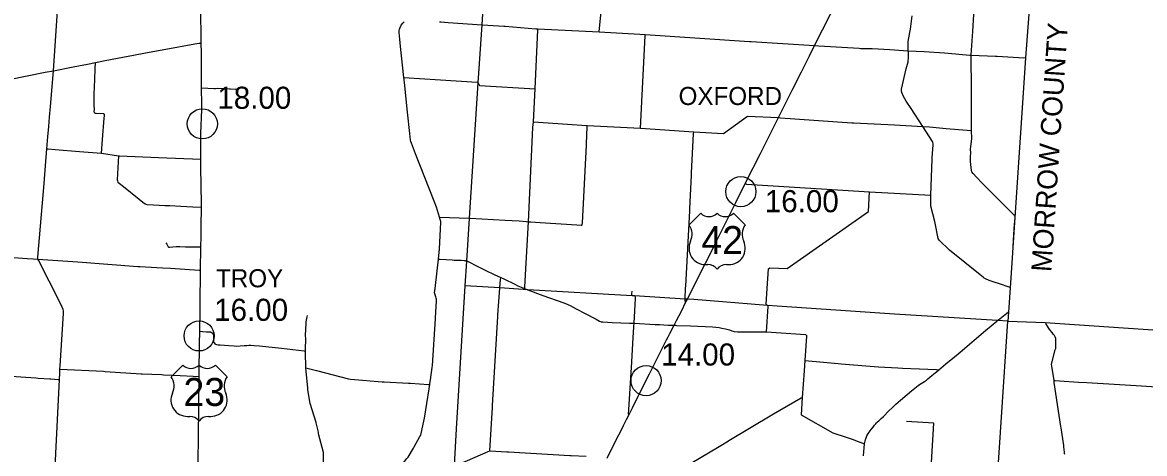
# Model space of a CAD drawing. Extents: x 1597222 to 1925846, y 496284 to 911751.
# Drawn here: x 1799698 to 1855559, y 852560 to 874016 of the extents above; entities that cross this region are included whole.
import ezdxf

# ---------------------------------------------------------------- set-up
doc = ezdxf.new("R2010")
doc.units = 0
for name, color, linetype in [('Default', 7, 'Continuous'), ('GM_X_Adjacent_County_Text', 7, 'Continuous'), ('GM_X_County', 7, 'Continuous'), ('GM_X_County_Road', 7, 'Continuous'), ('GM_X_Township', 7, 'Continuous'), ('GM_X_Township_Road', 7, 'Continuous'), ('GM_X_Township_Text', 7, 'Continuous'), ('GM_X_US_Route', 7, 'Continuous'), ('GM_X_US_Shield', 7, 'Continuous')]:
    doc.layers.add(name, color=color, linetype=linetype)

msp = doc.modelspace()

# ---------------------------------------------------------------- linework, layer by layer
at = {"layer": 'Default'}
for centre in [(1808652, 868968), (1835461, 865595), (1808492, 858414), (1830743, 856190)]:
    msp.add_circle(centre, 750, dxfattribs=at)
at = {"layer": 'GM_X_County'}
msp.add_lwpolyline([(1850017, 877290), (1849634, 872258), (1849106, 864311), (1848864, 860810), (1848787, 859601), (1848752, 859146), (1850615, 859080), (1861827, 858324)], dxfattribs=at)
at = {"layer": 'GM_X_County_Road'}
for points in [[(1801238, 871613), (1801481, 875086), (1801483, 875120), (1801484, 875131)], [(1844920, 865421), (1844988, 867215), (1844990, 867274), (1845035, 867925), (1845034, 867981), (1845022, 868042), (1845000, 868095), (1844527, 868834), (1843932, 869740), (1843693, 870106), (1843565, 870325), (1843478, 870530), (1843453, 870621), (1843455, 870702), (1843691, 871703), (1843783, 872054), (1843799, 872125), (1843808, 872218), (1843813, 872294), (1843800, 872513), (1843796, 872610), (1843794, 872719), (1843797, 872872), (1843799, 873058), (1843810, 873171), (1843903, 873683), (1843995, 874339)], [(1820462, 864324), (1820315, 864828), (1820199, 865126), (1819267, 867478), (1819059, 868009), (1819037, 868087), (1819024, 868161), (1818988, 868490), (1818871, 869545), (1818714, 871024), (1818688, 871275), (1818522, 872824), (1818481, 873185), (1818449, 873518), (1818456, 873613), (1818468, 873675), (1818498, 873766), (1818559, 873888), (1818627, 873984), (1818695, 874040)], [(1824699, 860768), (1824709, 860807), (1824715, 860860), (1824883, 864100), (1825114, 868796), (1825134, 869072), (1825228, 870716), (1825347, 873642), (1825350, 873697)], [(1825350, 873697), (1828404, 873550), (1830426, 873436), (1830706, 873421), (1835899, 873073), (1835968, 873069), (1839135, 872864)], [(1796250, 870609), (1800830, 871534), (1801238, 871613), (1802216, 871813), (1802942, 871947), (1803327, 872024), (1803819, 872121), (1804436, 872238), (1805225, 872387), (1805820, 872499), (1807386, 872793), (1807725, 872855), (1808371, 872970), (1808499, 872991), (1808602, 872989)], [(1839135, 872864), (1839344, 872852), (1841345, 872730), (1841421, 872727), (1842003, 872716), (1842870, 872667), (1843552, 872620), (1843796, 872610)], [(1801567, 856755), (1801567, 856755), (1801584, 856930), (1801742, 859524), (1801746, 859662), (1801732, 859727), (1801677, 859846), (1801556, 860087), (1800489, 862190), (1800471, 862240), (1800469, 862342), (1800776, 866006), (1800811, 866452), (1800848, 866888), (1800911, 867730), (1800965, 868323), (1801008, 868838), (1801046, 869299), (1801092, 869835), (1801238, 871613)], [(1848869, 860822), (1848289, 861017), (1848127, 861070), (1847820, 861177), (1847644, 861252), (1847581, 861290), (1847540, 861317), (1847370, 861450), (1845855, 862679), (1845795, 862727), (1845378, 863132), (1845338, 863172), (1845282, 863256), (1845130, 864033), (1845116, 864109), (1844927, 864878), (1844914, 864930), (1844919, 865353), (1844920, 865421)], [(1819979, 856052), (1820004, 856221), (1820093, 856849), (1820106, 856948), (1820253, 859267), (1820256, 859321), (1820308, 860164), (1820312, 860243), (1820295, 860293), (1820272, 860358), (1820219, 860562), (1820238, 860767), (1820341, 861658), (1820408, 862232), (1820454, 862755), (1820524, 864057), (1820528, 864114), (1820480, 864265), (1820462, 864324)], [(1820408, 862232), (1820494, 862231), (1821085, 862203), (1821196, 862192), (1821533, 862179), (1821692, 862169), (1821732, 862161)], [(1821732, 862161), (1821747, 862158), (1821783, 862149), (1821820, 862138), (1821852, 862127), (1822363, 861870), (1822764, 861678), (1823175, 861477), (1823506, 861322), (1823697, 861236), (1824174, 861011), (1824367, 860911), (1824699, 860768)], [(1824699, 860768), (1824857, 860710), (1825612, 860430), (1826656, 860059), (1826853, 859982), (1826971, 859934), (1827258, 859768), (1827710, 859527), (1828254, 859247), (1828432, 859153), (1828513, 859123), (1828584, 859112), (1829052, 859088), (1829917, 859051), (1830145, 859048), (1831204, 858991), (1831412, 858982), (1831846, 858956), (1831978, 858953), (1832140, 858950)], [(1813792, 857659), (1813794, 857827), (1813800, 858197), (1813802, 858295), (1813794, 858400), (1813790, 858459), (1813824, 859039), (1813828, 859109), (1813877, 859368), (1813888, 859424)], [(1841560, 852444), (1841625, 853051), (1841645, 853178), (1841666, 853257), (1841678, 853296), (1841734, 853436), (1841775, 853522), (1841811, 853578), (1841852, 853630), (1841955, 853751), (1842050, 853872), (1842120, 853970), (1842174, 854044), (1842213, 854090), (1842257, 854132), (1842328, 854190), (1842398, 854247), (1842454, 854298), (1842569, 854408), (1842835, 854682), (1843009, 854858), (1843082, 854926), (1843184, 855026), (1843290, 855116), (1843408, 855218), (1843743, 855499), (1843955, 855674), (1844282, 855947), (1844355, 856000), (1844431, 856051), (1844597, 856149), (1844696, 856217), (1844777, 856277), (1844977, 856441), (1845142, 856580), (1845198, 856628), (1845320, 856733), (1845665, 857022), (1846093, 857374), (1846284, 857524), (1846382, 857614), (1847073, 858199), (1847645, 858684), (1848208, 859149), (1848243, 859177), (1848285, 859211), (1848293, 859218)], [(1848293, 859218), (1848788, 859619)], [(1808526, 858649), (1808657, 858638), (1808859, 858626), (1809019, 858618), (1809052, 858615), (1809095, 858599), (1809143, 858567), (1809166, 858544), (1809192, 858504), (1809208, 858460), (1809213, 858422), (1809211, 858321), (1809207, 858185), (1809213, 858132), (1809225, 858094), (1809243, 858063), (1809274, 858027), (1809305, 858005), (1809359, 857983), (1809445, 857973), (1809547, 857964), (1809965, 857932), (1810245, 857914), (1810373, 857908), (1810529, 857918), (1810728, 857939), (1810862, 857945), (1810963, 857947), (1811066, 857950), (1811236, 857941), (1811500, 857918), (1812600, 857811), (1813718, 857665), (1813792, 857659)], [(1832140, 858950), (1832225, 858943), (1832265, 858939), (1832961, 858909), (1834057, 858860), (1834388, 858837), (1834514, 858807), (1834697, 858768), (1834897, 858714), (1835014, 858675), (1835136, 858637), (1835294, 858625), (1835692, 858625), (1836196, 858623), (1836448, 858626), (1836739, 858621)], [(1836739, 858621), (1838675, 858491), (1838704, 858476), (1838715, 858460)], [(1851584, 852517), (1851577, 852569), (1851568, 852637), (1851545, 852900), (1851540, 852956), (1851400, 853843), (1851390, 853908), (1851065, 856102), (1851052, 856192), (1850945, 856903), (1850930, 857004), (1851117, 857720), (1851136, 857792), (1851143, 857929), (1851137, 858286), (1851111, 858362), (1851070, 858431), (1851029, 858488), (1850952, 858587), (1850847, 858724), (1850809, 858773), (1850694, 858953), (1850650, 859027)], [(1838715, 858460), (1838725, 858446), (1838731, 858409), (1838644, 857189), (1838612, 856680), (1838509, 855352), (1838468, 854485), (1840033, 853588), (1840704, 853369), (1840998, 853268), (1841304, 853162), (1841625, 853051)], [(1813810, 856819), (1813800, 856979), (1813794, 857454), (1813792, 857659)], [(1801549, 856244), (1801549, 856244), (1801565, 856560), (1801567, 856755)], [(1801567, 856755), (1803730, 856654), (1803812, 856649), (1805603, 856528), (1805663, 856523)], [(1813810, 856819), (1814272, 856708), (1814342, 856691), (1815928, 856285), (1816023, 856260), (1817602, 856132), (1817706, 856124), (1818919, 856063), (1819010, 856058), (1819906, 856004), (1819971, 856000)], [(1814317, 854102), (1814022, 855049), (1813998, 855126), (1813913, 855754), (1813904, 855818), (1813815, 856658), (1813810, 856819)], [(1801256, 850553), (1801549, 856244)], [(1816452, 847455), (1816586, 847751), (1818021, 850937), (1818081, 851052), (1818426, 851791), (1818463, 851867), (1818600, 852027), (1818667, 852103), (1818835, 852306), (1818895, 852378), (1819166, 852831), (1819205, 852895), (1819487, 853403), (1819531, 853481), (1819699, 854255), (1819715, 854325), (1819940, 855787), (1819971, 856000), (1819979, 856052)], [(1814694, 851004), (1814695, 851266), (1814689, 851950), (1814688, 852505), (1814683, 852620), (1814444, 853547), (1814429, 853618), (1814335, 854030), (1814321, 854092), (1814317, 854102)]]:
    msp.add_lwpolyline(points, dxfattribs=at)
at = {"layer": 'GM_X_Township'}
for points in [[(1850017, 877290), (1849634, 872258), (1849106, 864311), (1848864, 860810), (1848787, 859601), (1848752, 859146), (1848243, 859177), (1843111, 859493), (1837275, 859897), (1836785, 859928), (1833125, 860220), (1832799, 860239), (1832694, 860243), (1830166, 860402), (1830089, 860410), (1830057, 860416), (1824857, 860710), (1823464, 860801), (1821743, 860915), (1821820, 862138), (1821956, 864281), (1822382, 871013), (1822583, 873901), (1822822, 877662)], [(1820182, 834021), (1820274, 835623), (1820357, 837080), (1820411, 838018), (1820789, 844650), (1820950, 847472), (1821204, 851968), (1821306, 853784), (1821743, 860915)], [(1858606, 831851), (1854821, 832136), (1851310, 832334), (1849737, 832422), (1846971, 832575), (1847065, 833986), (1848030, 848046), (1848128, 849585), (1848752, 859146), (1850615, 859080), (1861827, 858324)]]:
    msp.add_lwpolyline(points, dxfattribs=at)
at = {"layer": 'GM_X_Township_Road'}
for points in [[(1828404, 873550), (1828535, 874900), (1828545, 874985), (1828797, 877614), (1828805, 877701), (1828926, 878930)], [(1846952, 868642), (1846950, 869189), (1846940, 869904), (1846940, 870264), (1846936, 871157), (1846927, 871876), (1846924, 872189), (1846924, 872391), (1846924, 872409), (1846974, 873096), (1847017, 873560), (1847077, 874700), (1847167, 875719), (1847252, 876799), (1847310, 877457)], [(1820460, 874051), (1820518, 874039), (1820891, 874015), (1822583, 873901), (1822593, 873900)], [(1822593, 873900), (1823661, 873833), (1823727, 873829), (1825253, 873705), (1825350, 873697)], [(1830464, 868756), (1830701, 873344), (1830706, 873421)], [(1843796, 872610), (1844591, 872563), (1845606, 872508), (1846865, 872395), (1846924, 872391), (1848139, 872336), (1848226, 872331), (1849545, 872262), (1849640, 872268)], [(1803268, 870443), (1803301, 871169), (1803323, 871703), (1803327, 872024)], [(1818688, 871275), (1822342, 871039), (1822367, 871038)], [(1822367, 871038), (1822368, 871038), (1822382, 871013), (1822458, 870878), (1825228, 870716)], [(1803630, 867510), (1803691, 868196), (1803773, 869260), (1803782, 869375), (1803783, 869405), (1803781, 869425), (1803775, 869439), (1803764, 869452), (1803746, 869464), (1803713, 869468), (1803374, 869487), (1803312, 869492), (1803294, 869504), (1803281, 869529), (1803275, 869558), (1803280, 869733), (1803274, 869853), (1803267, 870424), (1803268, 870443)], [(1808615, 870762), (1809236, 870737), (1809316, 870737), (1809432, 870743), (1809843, 870725), (1810007, 870717), (1810039, 870714), (1810063, 870708), (1810302, 870697), (1810369, 870694)], [(1825134, 869072), (1827790, 868881), (1827808, 868880), (1830464, 868756), (1833115, 868570), (1834606, 868488), (1835796, 869350), (1837331, 869279), (1837434, 869271)], [(1837434, 869271), (1840984, 869021), (1841014, 869019), (1841088, 869014), (1843104, 868927), (1844527, 868834), (1844860, 868817), (1845680, 868730), (1846299, 868685), (1846723, 868656), (1846952, 868642)], [(1824883, 864100), (1825008, 864087), (1825479, 864057), (1827301, 863943), (1827512, 863928), (1827528, 863927), (1827544, 863932), (1827556, 863942), (1827563, 863956), (1827574, 864035), (1827772, 867912), (1827777, 867978), (1827806, 868822), (1827808, 868880)], [(1847190, 866322), (1847029, 866494), (1846966, 866586), (1846940, 866643), (1846902, 867096), (1846899, 867328), (1846913, 867520), (1846901, 867711), (1846907, 867849), (1846949, 868098), (1846958, 868238), (1846952, 868642)], [(1832712, 860086), (1832692, 860180), (1832694, 860243), (1832711, 860815), (1832717, 860894), (1832916, 864638), (1832920, 864735), (1833003, 866422), (1833008, 866525), (1833111, 868476), (1833115, 868570)], [(1800911, 867730), (1800986, 867727), (1801330, 867699), (1802540, 867596), (1803630, 867510), (1804477, 867384), (1804498, 867383), (1804527, 867381)], [(1804477, 867384), (1804421, 866175), (1804424, 866127), (1804449, 866069), (1804513, 866012), (1804732, 865849), (1805503, 865225), (1805691, 865068), (1805810, 864983), (1805846, 864967), (1805905, 864963), (1806229, 864943), (1806794, 864904), (1807037, 864899), (1807575, 864865), (1808185, 864842), (1808605, 864823)], [(1804527, 867381), (1806474, 867297)], [(1806474, 867297), (1808579, 867207)], [(1835681, 865996), (1835751, 865973), (1841870, 865582), (1844920, 865421)], [(1849108, 864379), (1849086, 864409), (1849077, 864422), (1849056, 864444), (1848707, 864795), (1848132, 865354), (1847476, 866016), (1847190, 866322)], [(1836801, 859906), (1836785, 859928), (1836730, 860003), (1836772, 860771), (1836832, 861759), (1836900, 861806), (1837774, 861777), (1841815, 864609), (1841870, 865582)], [(1820462, 864324), (1821937, 864282)], [(1821937, 864282), (1821956, 864281), (1821991, 864279), (1823727, 864175), (1824431, 864135), (1824774, 864114), (1824883, 864100)], [(1849021, 862856), (1849057, 863463), (1849090, 863978), (1849102, 864092), (1849117, 864321), (1849117, 864329), (1849117, 864338), (1849117, 864343), (1849117, 864351), (1849116, 864355), (1849116, 864358), (1849115, 864361), (1849113, 864368), (1849111, 864373), (1849108, 864379)], [(1795573, 862604), (1795573, 862604), (1798801, 862345), (1799934, 862267), (1800231, 862253), (1800471, 862240)], [(1806832, 863051), (1806885, 862986), (1806910, 862940), (1806928, 862878), (1806946, 862853), (1806969, 862836), (1807015, 862834), (1807358, 862860), (1807384, 862860), (1807529, 862858), (1807823, 862841), (1807878, 862841), (1808114, 862844), (1808408, 862851), (1808584, 862855)], [(1800471, 862240), (1802462, 862095), (1805449, 861870), (1805545, 861864), (1806678, 861809), (1807065, 861779), (1808492, 861691), (1808564, 861690)], [(1823464, 860797), (1823464, 860801), (1823489, 861218), (1823506, 861322)], [(1822973, 852697), (1823090, 854855), (1823095, 854950), (1823360, 859378), (1823364, 859462), (1823464, 860797)], [(1830145, 859048), (1830219, 860280), (1830222, 860351), (1830198, 860382), (1830166, 860402), (1830089, 860410), (1830057, 860416), (1830033, 860449), (1830040, 860509), (1830047, 860642)], [(1836739, 858621), (1836819, 859882), (1836801, 859906)], [(1829879, 854468), (1829867, 854539), (1829884, 854733), (1829968, 856079), (1830015, 856843), (1830104, 858325), (1830133, 858863), (1830135, 858890)], [(1830135, 858890), (1830145, 859048)], [(1838644, 857189), (1839578, 857114), (1840298, 857042)], [(1840298, 857042), (1840462, 857025), (1841078, 856968), (1841688, 856928), (1842311, 856878), (1843277, 856832), (1843501, 856817), (1844772, 856764), (1845200, 856735), (1845320, 856733)], [(1795090, 856488), (1796016, 856428), (1796449, 856346), (1796551, 856339), (1796604, 856337), (1796665, 856335), (1796771, 856339), (1796829, 856341), (1797357, 856367), (1797448, 856371), (1797816, 856403), (1797914, 856411), (1798495, 856434), (1798591, 856437), (1798633, 856451), (1800371, 856321), (1800474, 856313), (1801054, 856281), (1801112, 856277), (1801481, 856249), (1801549, 856244)], [(1805663, 856523), (1806613, 856487), (1806716, 856483), (1807543, 856452), (1808194, 856410), (1808493, 856392)], [(1851052, 856192), (1851109, 856192), (1851317, 856179), (1852272, 856121), (1852677, 856096), (1855405, 855928), (1855903, 855897), (1856892, 855832)], [(1834871, 853208), (1837006, 854484), (1837090, 854534), (1838463, 855326), (1838509, 855352)], [(1844768, 849049), (1845076, 854067), (1843711, 854157), (1843711, 854157)], [(1829632, 850131), (1829670, 850148), (1829937, 850308), (1830715, 850775), (1831571, 851235), (1831618, 851263), (1834382, 852917), (1834467, 852967), (1834850, 853196), (1834871, 853208)], [(1821238, 851978), (1821378, 852020), (1821474, 852048), (1822880, 852657), (1822973, 852697), (1822981, 852696), (1823816, 852647), (1823896, 852643), (1826953, 852461), (1827020, 852457), (1827766, 852423)]]:
    msp.add_lwpolyline(points, dxfattribs=at)
at = {"layer": 'GM_X_US_Route'}
for points in [[(1808595, 873359), (1808593, 873477), (1808580, 874305), (1808584, 874680), (1808589, 875164), (1808584, 876236), (1808583, 877272), (1808564, 878356), (1808567, 879838), (1808589, 880869), (1808563, 882458), (1808556, 883637), (1808559, 883718)], [(1832814, 860270), (1833045, 860728), (1833707, 862039), (1833995, 862623), (1834269, 863162), (1835215, 865051), (1835681, 865996), (1836078, 866774), (1836442, 867502), (1837331, 869279), (1837642, 869882), (1838022, 870648), (1838475, 871555), (1838873, 872351), (1839135, 872864), (1840316, 875226), (1840905, 876404)], [(1808574, 868253), (1808573, 868508), (1808622, 869660), (1808622, 869931), (1808615, 870762), (1808609, 871383), (1808606, 872500), (1808602, 872989), (1808595, 873359)], [(1808580, 867154), (1808579, 867207), (1808575, 868049), (1808574, 868253)], [(1808593, 863493), (1808595, 863872), (1808605, 864823), (1808590, 866059), (1808585, 866653), (1808583, 866893), (1808580, 867154)], [(1808531, 859016), (1808538, 859249), (1808549, 859969), (1808564, 861690), (1808584, 862855), (1808592, 863349), (1808593, 863493)], [(1830354, 855412), (1830390, 855482), (1830910, 856524), (1831328, 857349), (1831761, 858212), (1831835, 858364), (1831922, 858529), (1832140, 858950), (1832178, 859024), (1832261, 859187), (1832516, 859678), (1832712, 860086), (1832799, 860239), (1832814, 860270)], [(1808510, 857628), (1808515, 857996), (1808526, 858649), (1808531, 858995), (1808531, 859016)], [(1808437, 851954), (1808441, 852097), (1808474, 854817), (1808493, 856392), (1808501, 857014), (1808510, 857555), (1808510, 857628)], [(1829567, 853847), (1829623, 853958), (1829773, 854260), (1829879, 854468), (1830065, 854836), (1830354, 855412)], [(1828794, 852323), (1828817, 852370), (1829042, 852803), (1829388, 853493), (1829567, 853847)]]:
    msp.add_lwpolyline(points, dxfattribs=at)
at = {"layer": 'GM_X_US_Shield'}
for p, q in [((1833468, 864520), (1832888, 863940)), ((1833468, 864520), (1832888, 863940)), ((1835673, 863940), (1835092, 864520)), ((1835673, 863940), (1835092, 864520)), ((1833700, 861967), (1833816, 861967)), ((1833700, 861967), (1833816, 861967)), ((1834744, 861967), (1834860, 861967)), ((1834744, 861967), (1834860, 861967)), ((1807680, 856960), (1807100, 856380)), ((1807680, 856960), (1807100, 856380)), ((1809884, 856380), (1809304, 856960)), ((1809884, 856380), (1809304, 856960)), ((1807912, 854408), (1808028, 854408)), ((1807912, 854408), (1808028, 854408)), ((1808956, 854408), (1809072, 854408)), ((1808956, 854408), (1809072, 854408))]:
    msp.add_line(p, q, dxfattribs=at)
for centre, radius, start, end in [((1833874, 864934), 580, 225.573, 314.427), ((1833874, 864934), 580, 225.573, 314.427), ((1834686, 864934), 580, 225.573, 314.427), ((1834686, 864934), 580, 225.573, 314.427), ((1832223, 863474), 812, 334.5471, 35.0009), ((1832223, 863474), 812, 334.5471, 35.0009), ((1836338, 863474), 812, 144.9991, 205.4529), ((1836338, 863474), 812, 144.9991, 205.4529), ((1833691, 862779), 812, 154.8319, 270.6383), ((1833691, 862779), 812, 154.8319, 270.6383), ((1834869, 862779), 812, 269.3617, 25.1681), ((1834869, 862779), 812, 269.3617, 25.1681), ((1833816, 861387), 580, 36.8699, 90), ((1833816, 861387), 580, 36.8699, 90), ((1834744, 861387), 580, 90, 143.1301), ((1834744, 861387), 580, 90, 143.1301), ((1808086, 857375), 580, 225.573, 314.427), ((1808086, 857375), 580, 225.573, 314.427), ((1808898, 857375), 580, 225.573, 314.427), ((1808898, 857375), 580, 225.573, 314.427), ((1806435, 855915), 812, 334.5471, 35.0009), ((1806435, 855915), 812, 334.5471, 35.0009), ((1810549, 855915), 812, 144.9991, 205.4529), ((1810549, 855915), 812, 144.9991, 205.4529), ((1807903, 855220), 812, 154.8319, 270.6383), ((1807903, 855220), 812, 154.8319, 270.6383), ((1809081, 855220), 812, 269.3617, 25.1681), ((1809081, 855220), 812, 269.3617, 25.1681), ((1808028, 853828), 580, 36.8699, 90), ((1808028, 853828), 580, 36.8699, 90), ((1808956, 853828), 580, 90, 143.1301), ((1808956, 853828), 580, 90, 143.1301)]:
    msp.add_arc(centre, radius, start, end, dxfattribs=at)

# ---------------------------------------------------------------- texts
at = {"layer": 'Default'}
for s, p in [('18.00', (1809402, 869718)), ('16.00', (1836655, 864571)), ('16.00', (1809242, 859164)), ('14.00', (1831493, 856940))]:
    msp.add_text(s, height=1100, dxfattribs=at).set_placement(p)
at = {"layer": 'GM_X_Adjacent_County_Text'}
msp.add_text('MORROW COUNTY', height=1000, rotation=86.16, dxfattribs=at).set_placement((1850915, 861578))
at = {"layer": 'GM_X_Township_Text'}
for s, p in [('OXFORD', (1832362, 869907)), ('TROY', (1809335, 860835))]:
    msp.add_text(s, height=900, rotation=0, dxfattribs=at).set_placement(p)
at = {"layer": 'GM_X_US_Shield'}
for s, p in [('42', (1833497, 862489)), ('42', (1833497, 862489)), ('23', (1807717, 854930)), ('23', (1807717, 854930))]:
    msp.add_text(s, height=1392.2, dxfattribs=at).set_placement(p)

doc.saveas('drawing.dxf')
